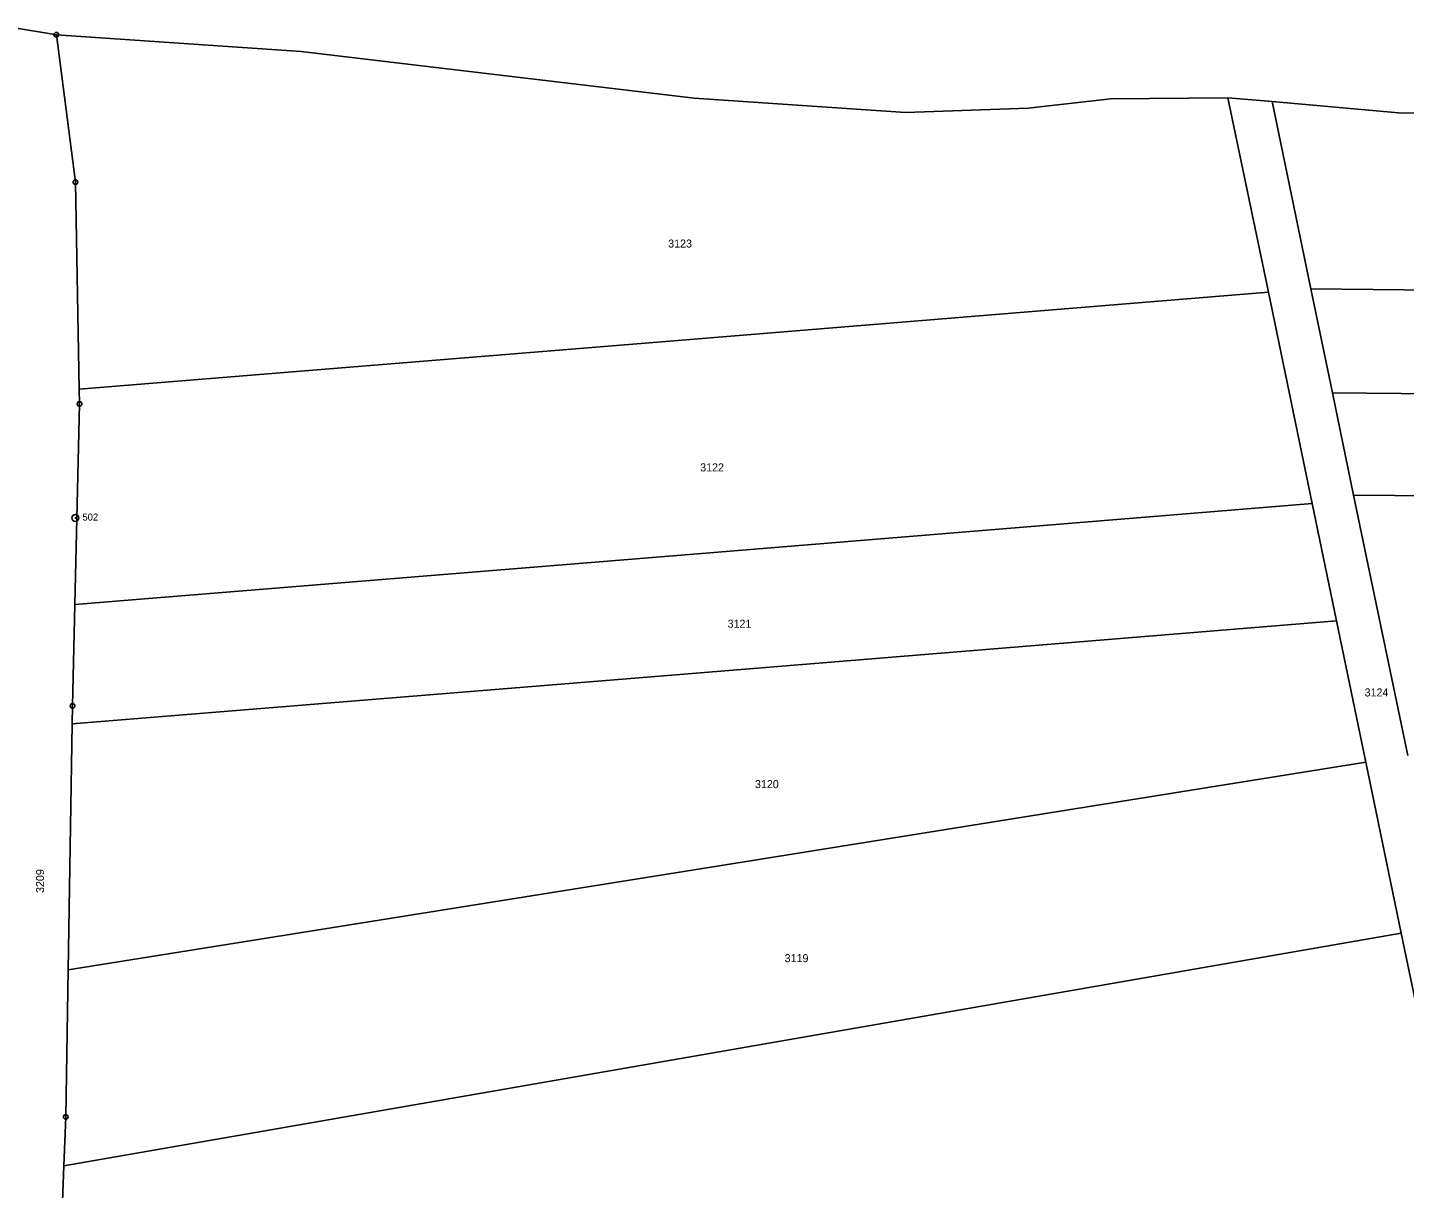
# Model space of a CAD drawing. Extents: x -618848 to -615803, y -1044450 to -1042254.
# Drawn here: x -617038.7 to -616746.1, y -1042523.1 to -1042276.5 of the extents above; entities that cross this region are included whole.
import ezdxf

# ---------------------------------------------------------------- set-up
doc = ezdxf.new("R2010")
doc.units = 0
doc.header["$LTSCALE"] = 0.68
doc.layers.add('1', color=7, linetype='Continuous', lineweight=25)
doc.layers.add('8', color=7, linetype='Continuous', lineweight=25)
doc.layers.add('2', color=7, linetype='Continuous')

msp = doc.modelspace()

# ---------------------------------------------------------------- linework, layer by layer
at = {"layer": '1'}
for p, q in [((-617041.94, -1042276.47), (-617035.84, -1042277.46)), ((-617035.84, -1042277.46), (-617032.55, -1042278)), ((-617032.55, -1042278), (-616980.54, -1042281.56)), ((-617028.49, -1042309.31), (-617032.55, -1042278)), ((-616980.54, -1042281.56), (-616897.06, -1042291.44)), ((-616897.06, -1042291.44), (-616852.12, -1042294.55)), ((-616783.61, -1042291.38), (-616774.25, -1042292.21)), ((-616775.03, -1042332.71), (-616783.61, -1042291.38)), ((-616852.12, -1042294.55), (-616826.04, -1042293.59)), ((-616774.25, -1042292.21), (-616766, -1042331.97)), ((-617027.68, -1042353.29), (-617028.49, -1042309.31)), ((-616775.03, -1042332.71), (-616901.36, -1042343)), ((-616765.71, -1042377.6), (-616775.03, -1042332.71)), ((-616766, -1042331.97), (-616761.42, -1042354.06)), ((-616766, -1042331.97), (-616635.96, -1042333.24)), ((-616901.36, -1042343), (-617027.68, -1042353.29)), ((-617027.62, -1042356.42), (-617027.68, -1042353.29)), ((-616761.42, -1042354.06), (-616756.91, -1042375.78)), ((-616761.42, -1042354.06), (-616629.12, -1042355.35)), ((-617028.61, -1042399.03), (-617027.62, -1042356.42)), ((-616756.91, -1042375.78), (-616745.43, -1042431.11)), ((-616756.91, -1042375.78), (-616622.39, -1042377.09)), ((-616897.16, -1042388.32), (-616765.71, -1042377.6)), ((-616760.55, -1042402.52), (-616765.71, -1042377.6)), ((-617028.61, -1042399.03), (-616897.16, -1042388.32)), ((-617029.11, -1042420.58), (-617028.61, -1042399.03)), ((-616760.55, -1042402.52), (-616894.86, -1042413.46)), ((-616754.33, -1042432.51), (-616760.55, -1042402.52)), ((-616894.86, -1042413.46), (-617029.17, -1042424.41)), ((-617029.17, -1042424.41), (-617029.11, -1042420.58)), ((-617030.04, -1042476.69), (-617029.17, -1042424.41)), ((-616892.18, -1042454.6), (-616754.33, -1042432.51)), ((-616746.8, -1042468.84), (-616754.33, -1042432.51)), ((-617030.04, -1042476.69), (-616892.18, -1042454.6)), ((-616746.8, -1042468.84), (-616888.88, -1042493.57)), ((-616732.14, -1042539.47), (-616746.8, -1042468.84)), ((-617030.56, -1042507.91), (-617030.04, -1042476.69)), ((-616888.88, -1042493.57), (-617030.97, -1042518.3)), ((-617030.97, -1042518.3), (-617030.56, -1042507.91)), ((-617032.56, -1042559.13), (-617030.97, -1042518.3))]:
    msp.add_line(p, q, dxfattribs=at)
for points in [[(-616826.04, -1042293.59), (-616808.59, -1042291.63), (-616783.61, -1042291.38)], [(-616774.25, -1042292.21), (-616747.35, -1042294.61), (-616712.8, -1042294.65)]]:
    msp.add_lwpolyline(points, dxfattribs=at)
at = {"layer": '8'}
for centre, radius in [((-617032.55, -1042277.9999), 0.5), ((-617032.55, -1042277.9999), 0.0303), ((-617028.49, -1042309.3099), 0.5), ((-617028.49, -1042309.3099), 0.0303), ((-617027.62, -1042356.4199), 0.5), ((-617027.62, -1042356.4199), 0.0303), ((-617028.5, -1042380.6498), 0.75), ((-617028.5, -1042380.6498), 0.03), ((-617029.11, -1042420.5799), 0.5), ((-617029.11, -1042420.5799), 0.0303), ((-617030.56, -1042507.9099), 0.5), ((-617030.56, -1042507.9099), 0.0303)]:
    msp.add_circle(centre, radius, dxfattribs=at)

# ---------------------------------------------------------------- texts
at = {"layer": '2'}
for s, p in [('3123', (-616902.55, -1042323.205)), ('3122', (-616895.75, -1042370.765)), ('3121', (-616889.93, -1042403.975)), ('3124', (-616754.59, -1042418.575)), ('3120', (-616884.11, -1042438.045)), ('3119', (-616877.81, -1042475.025))]:
    msp.add_text(s, height=1.7, dxfattribs=at).set_placement(p)
msp.add_text('3209', height=1.7, rotation=90, dxfattribs=at).set_placement((-617035.165, -1042460.33))
at = {"layer": '8'}
msp.add_text('502', height=1.5, dxfattribs=at).set_placement((-617027.01, -1042381.215))

doc.saveas('drawing.dxf')
